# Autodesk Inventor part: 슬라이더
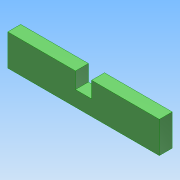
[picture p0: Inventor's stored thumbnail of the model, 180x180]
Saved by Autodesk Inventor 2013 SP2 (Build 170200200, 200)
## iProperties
Created: 2025-07
Part Number: 슬라이더
Material: Generic
Document SubType Name: Modeling
Designer: a
Density: 1 g/cm^3
Author: a
변환 표준: STEP AP214IS
전처리기: Build: 200, Release: 2013 SP2 Update 6 - Date: Thu 07/17/2014
전송 단위: 밀리미터
불확실성: 0.01
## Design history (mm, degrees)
node "슬라이더1"
node "솔리드1"
node "기준1"
